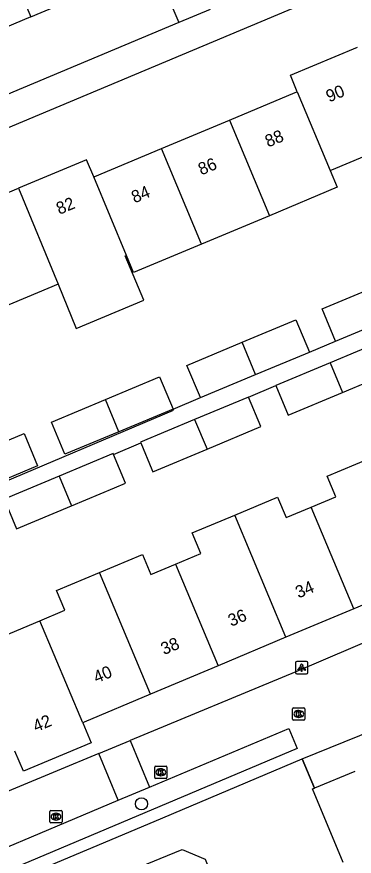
# Model space of a CAD drawing. Extents: x 157767 to 159171, y 387842 to 389425.
# Drawn here: x 158781.7 to 158809.2, y 388397.1 to 388465.6 of the extents above; entities that cross this region are included whole.
import ezdxf

# ---------------------------------------------------------------- set-up
doc = ezdxf.new("R2010")
doc.units = 0
for name, color, linetype in [('IMGEO_Boom', 7, 'Continuous'), ('IMGEO_Kolk', 7, 'Continuous'), ('IMGEO_Lichtpunt', 7, 'Continuous'), ('IMGEO_Muur', 7, 'Continuous'), ('IMGEO_Pand', 7, 'Continuous'), ('IMGEO_Pand_nummerreeks', 7, 'Continuous'), ('IMGEO_Rijbaan_lokaal_open', 7, 'Continuous'), ('IMGEO_Voetpad_open', 7, 'Continuous')]:
    doc.layers.add(name, color=color, linetype=linetype)

msp = doc.modelspace()

# ---------------------------------------------------------------- linework, layer by layer
at = {"layer": 'IMGEO_Boom'}
msp.add_circle((158791.846, 388401.376), 0.489, dxfattribs=at)
at = {"layer": 'IMGEO_Kolk'}
for p, q in [((158804.256, 388409.204), (158805.108, 388409.204)), ((158804.181, 388408.278), (158804.181, 388409.13)), ((158804.669, 388408.984), (158804.694, 388408.984)), ((158805.182, 388409.13), (158805.182, 388408.278)), ((158805.108, 388408.204), (158804.256, 388408.204)), ((158804.692, 388408.424), (158804.667, 388408.424)), ((158792.922, 388403.522), (158792.922, 388404.374)), ((158792.997, 388404.448), (158793.849, 388404.448)), ((158793.923, 388404.374), (158793.923, 388403.522)), ((158793.41, 388404.228), (158793.435, 388404.228)), ((158793.849, 388403.448), (158792.997, 388403.448)), ((158793.433, 388403.668), (158793.408, 388403.668)), ((158784.363, 388399.904), (158784.363, 388400.756)), ((158784.438, 388400.83), (158785.29, 388400.83)), ((158784.851, 388400.61), (158784.876, 388400.61)), ((158785.364, 388400.756), (158785.364, 388399.904)), ((158785.29, 388399.83), (158784.438, 388399.83)), ((158784.874, 388400.05), (158784.849, 388400.05))]:
    msp.add_line(p, q, dxfattribs=at)
for points in [[(158804.256, 388409.204), (158805.108, 388409.204)], [(158804.181, 388408.278), (158804.181, 388409.13)], [(158804.502, 388408.904), (158804.625, 388408.904), (158804.625, 388408.753), (158804.755, 388408.904), (158804.919, 388408.904), (158804.773, 388408.753), (158804.926, 388408.504), (158804.774, 388408.504), (158804.689, 388408.668), (158804.625, 388408.601), (158804.625, 388408.504), (158804.502, 388408.504), (158804.502, 388408.904)], [(158805.182, 388409.13), (158805.182, 388408.278)], [(158805.108, 388408.204), (158804.256, 388408.204)], [(158792.922, 388403.522), (158792.922, 388404.374)], [(158792.997, 388404.448), (158793.849, 388404.448)], [(158793.923, 388404.374), (158793.923, 388403.522)], [(158793.243, 388404.148), (158793.366, 388404.148), (158793.366, 388403.997), (158793.496, 388404.148), (158793.66, 388404.148), (158793.514, 388403.997), (158793.667, 388403.748), (158793.515, 388403.748), (158793.43, 388403.912), (158793.366, 388403.845), (158793.366, 388403.748), (158793.243, 388403.748), (158793.243, 388404.148)], [(158793.849, 388403.448), (158792.997, 388403.448)], [(158784.363, 388399.904), (158784.363, 388400.756)], [(158784.438, 388400.83), (158785.29, 388400.83)], [(158784.684, 388400.53), (158784.807, 388400.53), (158784.807, 388400.379), (158784.937, 388400.53), (158785.101, 388400.53), (158784.955, 388400.379), (158785.108, 388400.13), (158784.956, 388400.13), (158784.871, 388400.294), (158784.807, 388400.227), (158784.807, 388400.13), (158784.684, 388400.13), (158784.684, 388400.53)], [(158785.364, 388400.756), (158785.364, 388399.904)], [(158785.29, 388399.83), (158784.438, 388399.83)]]:
    msp.add_lwpolyline(points, dxfattribs=at)
for centre, start, end in [((158804.258, 388409.128), 91.55205, 178.44795), ((158804.258, 388409.128), 91.55205, 178.44795), ((158805.106, 388409.128), 1.55205, 88.44795), ((158805.106, 388409.128), 1.55205, 88.44795), ((158804.258, 388408.28), 181.55205, 268.44795), ((158804.258, 388408.28), 181.55205, 268.44795), ((158805.106, 388408.28), 271.55205, 358.44795), ((158805.106, 388408.28), 271.55205, 358.44795), ((158792.999, 388404.372), 91.55205, 178.44795), ((158792.999, 388404.372), 91.55205, 178.44795), ((158793.847, 388404.372), 1.55205, 88.44795), ((158793.847, 388404.372), 1.55205, 88.44795), ((158792.999, 388403.524), 181.55205, 268.44795), ((158792.999, 388403.524), 181.55205, 268.44795), ((158793.847, 388403.524), 271.55205, 358.44795), ((158793.847, 388403.524), 271.55205, 358.44795), ((158784.44, 388400.754), 91.55205, 178.44795), ((158784.44, 388400.754), 91.55205, 178.44795), ((158785.288, 388400.754), 1.55205, 88.44795), ((158785.288, 388400.754), 1.55205, 88.44795), ((158784.44, 388399.906), 181.55205, 268.44795), ((158784.44, 388399.906), 181.55205, 268.44795), ((158785.288, 388399.906), 271.55205, 358.44795), ((158785.288, 388399.906), 271.55205, 358.44795)]:
    msp.add_arc(centre, 0.0765, start, end, dxfattribs=at)
for centre, major_axis, ratio, start_param, end_param in [((158804.668, 388408.704), (-0.387, 0.002), 0.722429, 4.712389, 7.853982), ((158804.693, 388408.704), (-0.39, 0.002), 0.717154, 1.570796, 4.712389), ((158793.409, 388403.948), (-0.387, 0.002), 0.722429, 4.712389, 7.853982), ((158793.434, 388403.948), (-0.39, 0.002), 0.717154, 1.570796, 4.712389), ((158784.85, 388400.33), (-0.387, 0.002), 0.722429, 4.712389, 7.853982), ((158784.875, 388400.33), (-0.39, 0.002), 0.717154, 1.570796, 4.712389)]:
    msp.add_ellipse(centre, major_axis=major_axis, ratio=ratio, start_param=start_param, end_param=end_param, dxfattribs=at)
at = {"layer": 'IMGEO_Lichtpunt'}
for p, q in [((158804.419, 388412.884), (158804.419, 388412.077)), ((158804.419, 388412.884), (158804.419, 388412.077)), ((158805.321, 388412.979), (158804.513, 388412.979)), ((158805.321, 388412.979), (158804.513, 388412.979)), ((158805.415, 388412.077), (158805.415, 388412.884)), ((158805.415, 388412.077), (158805.415, 388412.884)), ((158804.513, 388411.983), (158805.321, 388411.983)), ((158804.513, 388411.983), (158805.321, 388411.983))]:
    msp.add_line(p, q, dxfattribs=at)
for points in [[(158804.793, 388412.548), (158804.832, 388412.52), (158804.644, 388412.258), (158804.606, 388412.285), (158804.793, 388412.548)], [(158804.895, 388412.5), (158804.942, 388412.5), (158804.942, 388412.178), (158804.895, 388412.178), (158804.895, 388412.5)], [(158805.005, 388412.52), (158805.043, 388412.547), (158805.23, 388412.285), (158805.191, 388412.257), (158805.005, 388412.52)]]:
    msp.add_lwpolyline(points, dxfattribs=at)
msp.add_circle((158804.918, 388412.682), 0.0994, dxfattribs=at)
for centre, start, end in [((158804.513, 388412.884), 90, 180), ((158804.513, 388412.884), 90, 180), ((158805.321, 388412.884), 0, 90), ((158805.321, 388412.884), 0, 90), ((158804.513, 388412.077), 180, 270), ((158804.513, 388412.077), 180, 270), ((158805.321, 388412.077), 270, 0), ((158805.321, 388412.077), 270, 360)]:
    msp.add_arc(centre, 0.0946, start, end, dxfattribs=at)
at = {"layer": 'IMGEO_Muur'}
for points in [[(158792.872, 388399.943), (158804.972, 388405.036)], [(158804.972, 388405.036), (158805.972, 388402.664)]]:
    msp.add_lwpolyline(points, dxfattribs=at)
at = {"layer": 'IMGEO_Pand'}
for points in [[(158804.562, 388459.444), (158803.997, 388460.797), (158809.47, 388463.083)], [(158799.023, 388457.13), (158804.399, 388459.376), (158804.562, 388459.444)], [(158804.562, 388459.444), (158807.246, 388453.018)], [(158793.484, 388454.817), (158799.023, 388457.13)], [(158799.023, 388457.13), (158802.28, 388449.336)], [(158812.674, 388455.286), (158807.351, 388453.062), (158807.246, 388453.018)], [(158787.946, 388452.503), (158788.048, 388452.546), (158793.484, 388454.817)], [(158796.741, 388447.022), (158793.484, 388454.817)], [(158787.946, 388452.503), (158787.367, 388453.889), (158781.809, 388451.568)], [(158807.246, 388453.018), (158807.818, 388451.65), (158802.28, 388449.336)], [(158790.62, 388446.101), (158787.946, 388452.503)], [(158776.901, 388447.842), (158776.29, 388449.262), (158781.809, 388451.568)], [(158781.809, 388451.568), (158785.03, 388443.765)], [(158802.28, 388449.336), (158796.741, 388447.022)], [(158796.741, 388447.022), (158791.202, 388444.708), (158790.62, 388446.101)], [(158785.03, 388443.765), (158786.522, 388440.15), (158792.027, 388442.45), (158790.519, 388446.058), (158790.62, 388446.101)], [(158785.03, 388443.765), (158779.627, 388441.508)], [(158807.688, 388439.11), (158806.591, 388441.737), (158811.159, 388443.645), (158812.256, 388441.019)], [(158800.063, 388439.01), (158804.454, 388440.844), (158805.551, 388438.217)], [(158807.688, 388439.11), (158812.256, 388441.019)], [(158796.655, 388434.5), (158795.557, 388437.127), (158800.063, 388439.01)], [(158801.16, 388436.382), (158800.063, 388439.01)], [(158811.657, 388439.183), (158807.248, 388437.341)], [(158808.26, 388434.93), (158812.665, 388436.771), (158811.657, 388439.183)], [(158801.16, 388436.382), (158805.225, 388438.08), (158805.551, 388438.217)], [(158807.248, 388437.341), (158802.809, 388435.486)], [(158807.248, 388437.341), (158808.26, 388434.93)], [(158788.906, 388434.348), (158793.327, 388436.195), (158794.425, 388433.568)], [(158796.655, 388434.5), (158801.16, 388436.382)], [(158802.809, 388435.486), (158803.817, 388433.074), (158808.26, 388434.93)], [(158800.57, 388434.55), (158796.181, 388432.716)], [(158797.193, 388430.306), (158801.578, 388432.138), (158800.57, 388434.55)], [(158790, 388431.72), (158785.594, 388429.879), (158784.497, 388432.506), (158788.906, 388434.348)], [(158790, 388431.72), (158788.906, 388434.348)], [(158794.425, 388433.568), (158790, 388431.72)], [(158796.181, 388432.716), (158791.751, 388430.866), (158791.778, 388430.802)], [(158796.181, 388432.716), (158797.193, 388430.306)], [(158777.85, 388429.729), (158782.271, 388431.576), (158783.369, 388428.949), (158778.948, 388427.102)], [(158791.778, 388430.802), (158792.677, 388428.651), (158792.759, 388428.454), (158797.193, 388430.306)], [(158789.549, 388429.87), (158789.522, 388429.934), (158785.115, 388428.093)], [(158786.127, 388425.683), (158789.642, 388427.152), (158790.53, 388427.522), (158789.549, 388429.87)], [(158805.687, 388425.568), (158807.71, 388426.417), (158807.009, 388428.086), (158810.516, 388429.558)], [(158785.115, 388428.093), (158780.646, 388426.226), (158780.675, 388426.156)], [(158785.115, 388428.093), (158786.127, 388425.683)], [(158799.454, 388424.922), (158802.956, 388426.392), (158803.66, 388424.717), (158805.687, 388425.568)], [(158780.675, 388426.156), (158781.654, 388423.814), (158786.127, 388425.683)], [(158794.63, 388420.92), (158796.685, 388421.783), (158795.979, 388423.463), (158799.454, 388424.922)], [(158803.64, 388414.955), (158799.454, 388424.922)], [(158809.169, 388417.276), (158805.687, 388425.568)], [(158788.415, 388420.234), (158791.932, 388421.711), (158792.618, 388420.076), (158794.63, 388420.92)], [(158794.63, 388420.92), (158798.11, 388412.633)], [(158783.557, 388416.312), (158785.592, 388417.166), (158784.92, 388418.767), (158788.415, 388420.234)], [(158792.581, 388410.311), (158788.415, 388420.234)], [(158814.698, 388419.598), (158809.169, 388417.276)], [(158809.169, 388417.276), (158803.64, 388414.955)], [(158778.028, 388413.99), (158783.557, 388416.312)], [(158787.051, 388407.99), (158783.557, 388416.312)], [(158803.64, 388414.955), (158798.11, 388412.633)], [(158798.11, 388412.633), (158792.581, 388410.311)], [(158792.581, 388410.311), (158787.162, 388408.036), (158787.051, 388407.99)], [(158787.051, 388407.99), (158787.735, 388406.361), (158782.205, 388404.039), (158781.518, 388405.675)], [(158809.25, 388404.026), (158805.972, 388402.664)], [(158808.311, 388396.589), (158805.814, 388402.598), (158805.972, 388402.664)], [(158785.947, 388387.225), (158784.954, 388389.653), (158788.401, 388391.063), (158787.06, 388394.341), (158795.153, 388397.652), (158797.044, 388396.859), (158797.677, 388395.314), (158799.25, 388395.957), (158800.321, 388395.507), (158801.168, 388393.441), (158798.142, 388392.205), (158795.234, 388391.018)]]:
    msp.add_lwpolyline(points, dxfattribs=at)
at = {"layer": 'IMGEO_Rijbaan_lokaal_open'}
for points in [[(158782.798, 388465.548), (158792.886, 388469.806)], [(158792.886, 388469.806), (158794.881, 388465.083)], [(158797.445, 388466.156), (158794.881, 388465.083)], [(158782.798, 388465.548), (158771.972, 388460.978)], [(158794.881, 388465.083), (158765.036, 388452.591)], [(158818.793, 388418.25), (158804.436, 388412.15), (158790.924, 388406.545)], [(158804.972, 388405.036), (158813.094, 388408.322)], [(158792.5, 388402.747), (158803.863, 388407.53), (158804.565, 388405.879), (158776.512, 388394.071)], [(158788.356, 388405.479), (158790.924, 388406.545)], [(158790.924, 388406.545), (158792.5, 388402.747)], [(158788.356, 388405.479), (158771.339, 388398.42)], [(158789.937, 388401.669), (158788.356, 388405.479)], [(158776.874, 388393.21), (158792.872, 388399.943), (158804.972, 388405.036)], [(158789.937, 388401.669), (158792.5, 388402.747)], [(158774.535, 388393.239), (158773.832, 388394.89), (158789.937, 388401.669)]]:
    msp.add_lwpolyline(points, dxfattribs=at)
at = {"layer": 'IMGEO_Voetpad_open'}
for points in [[(158806.667, 388475.624), (158806.017, 388477.164), (158782.125, 388467.147), (158782.798, 388465.548)], [(158815.471, 388470.983), (158747.081, 388442.3), (158745.672, 388438.649), (158746.324, 388437.057)], [(158805.551, 388438.217), (158807.688, 388439.11)], [(158800.57, 388434.55), (158802.809, 388435.486)], [(158794.425, 388433.568), (158796.655, 388434.5)], [(158762.364, 388420.099), (158778.899, 388426.909), (158794.46, 388433.477), (158794.425, 388433.568)], [(158789.549, 388429.87), (158791.778, 388430.802)], [(158805.972, 388402.664), (158804.972, 388405.036)]]:
    msp.add_lwpolyline(points, dxfattribs=at)

# ---------------------------------------------------------------- texts
at = {"layer": 'IMGEO_Pand_nummerreeks'}
for s, rotation, p in [('90', 22.66621, (158807.157, 388458.561)), ('88', 22.67194, (158802.179, 388454.893)), ('86', 22.67085, (158796.725, 388452.616)), ('84', 22.67194, (158791.275, 388450.338)), ('82', 22.67194, (158785.138, 388449.403)), ('34', 22.77662, (158804.66, 388418.117)), ('36', 22.77662, (158799.164, 388415.809)), ('38', 22.77662, (158793.671, 388413.502)), ('40', 22.77507, (158788.175, 388411.195)), ('42', 22.7808, (158783.232, 388407.203))]:
    msp.add_text(s, height=1, rotation=rotation, dxfattribs=at).set_placement(p)

doc.saveas('drawing.dxf')
